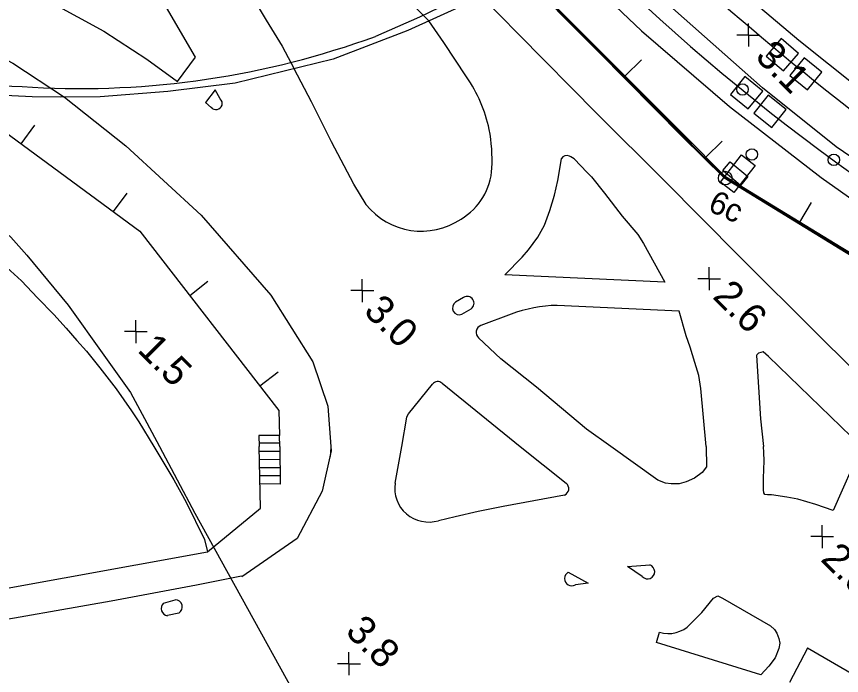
# Model space of a CAD drawing. Extents: x 1596643 to 1597288, y 13057194 to 13057957.
# Drawn here: x 1596778.7 to 1596850.7, y 13057439.2 to 13057496.7 of the extents above; entities that cross this region are included whole.
import ezdxf

# ---------------------------------------------------------------- set-up
doc = ezdxf.new("R2010")
doc.units = 0
for name, color, linetype in [('A spårmitt L', 7, 'Continuous'), ('B kabelbrunn mindre än 150 cm NK P', 7, 'Continuous'), ('BAS bro ej def L', 7, 'Continuous'), ('BAS fastighetsgräns samfällighet L', 7, 'Continuous'), ('BAS gränspunkt P', 7, 'Continuous'), ('BAS kajkant L', 7, 'Continuous'), ('BAS Level 15', 7, 'Continuous'), ('BAS Level 16', 7, 'Continuous'), ('BAS Level 18', 7, 'Continuous'), ('BAS Level 19', 7, 'Continuous'), ('BAS Level 37', 7, 'Continuous'), ('BAS markytetext T', 7, 'Continuous'), ('BAS stödmur fot L', 7, 'Continuous'), ('BAS stödmur krön L', 7, 'Continuous'), ('BAS trappa L', 7, 'Continuous'), ('BAS vägbanekant L', 7, 'Continuous'), ('BAS vägbanekant skymd L', 7, 'Continuous'), ('C skåp kartsymbol P', 7, 'Continuous'), ('D Plattform L', 7, 'Continuous'), ('E ktlstolpe omvriden centrum P', 7, 'Continuous'), ('E ktlstolpe T', 7, 'Continuous'), ('F balis P', 7, 'Continuous')]:
    doc.layers.add(name, color=color, linetype=linetype)

msp = doc.modelspace()

# ---------------------------------------------------------------- linework, layer by layer
at = {"layer": 'A spårmitt L'}
for centre, radius, start, end in [((1597037.43, 13057725.326), 301.08, 223.02589, 237.32659), ((1597036.217, 13057679.675), 257.932, 222.55623, 230.26648), ((1596962.077, 13057637.523), 190, 226.32199, 243.66622)]:
    msp.add_arc(centre, radius, start, end, dxfattribs=at)
at = {"layer": 'B kabelbrunn mindre än 150 cm NK P'}
msp.add_circle((1596842.862, 13057484.622), 0.5, dxfattribs=at)
msp.add_circle((1596842.862, 13057484.622), 0.5, dxfattribs=at)
at = {"layer": 'BAS bro ej def L'}
for points in [[(1596873.3, 13057525.881), (1596855.752, 13057517.013), (1596837.576, 13057507.614), (1596820.661, 13057499.012), (1596812.839, 13057495.445), (1596806.321, 13057492.938), (1596797.787, 13057490.834), (1596791.903, 13057490.118), (1596786.013, 13057489.635), (1596782.527, 13057489.62), (1596780.068, 13057489.652), (1596778.301, 13057489.746), (1596776.535, 13057489.911), (1596771.663, 13057490.412), (1596770.466, 13057490.58)], [(1596701.549, 13057432.918), (1596795.38, 13057449.947), (1596799.996, 13057453.759)]]:
    msp.add_lwpolyline(points, dxfattribs=at)
at = {"layer": 'BAS fastighetsgräns samfällighet L'}
for points in [[(1596648.373, 13057557.674), (1596669.206, 13057544.622), (1596696.734, 13057527.521), (1596729.513, 13057507.814), (1596732.164, 13057506.462), (1596736.214, 13057504.408), (1596755.642, 13057493.064), (1596764.143, 13057488.406), (1596767.219, 13057486.278), (1596770.569, 13057483.95), (1596773.669, 13057481.347), (1596776.843, 13057478.593), (1596778.218, 13057477.392), (1596779.593, 13057475.84), (1596783.217, 13057471.461), (1596786.315, 13057467.107), (1596788.639, 13057463.855), (1596790.088, 13057461.203), (1596791.175, 13057459.15)], [(1596791.175, 13057459.15), (1596794.26, 13057453.322), (1596807.425, 13057429.479), (1596823.36, 13057396.755), (1596830.03, 13057384.846), (1596831.279, 13057382.344)]]:
    msp.add_lwpolyline(points, dxfattribs=at)
at = {"layer": 'BAS gränspunkt P'}
for centre, radius in [((1596840.534, 13057482.562), 0.6), ((1596840.534, 13057482.562), 0.6), ((1596840.527, 13057482.557), 0.001), ((1596840.527, 13057482.557), 0.001)]:
    msp.add_circle(centre, radius, dxfattribs=at)
at = {"layer": 'BAS kajkant L'}
for points in [[(1596777.868, 13057474.754), (1596779.152, 13057473.579), (1596780.547, 13057472.119), (1596781.953, 13057470.649), (1596783.024, 13057469.466), (1596783.964, 13057468.394), (1596784.802, 13057467.445), (1596785.974, 13057465.986), (1596787.387, 13057464.171), (1596788.75, 13057462.254), (1596789.365, 13057461.296), (1596790.697, 13057459.15)], [(1596790.697, 13057459.15), (1596792.429, 13057456.23), (1596793.5, 13057454.271), (1596795.093, 13057451.023), (1596795.38, 13057449.947)]]:
    msp.add_lwpolyline(points, dxfattribs=at)
at = {"layer": 'BAS Level 15'}
for centre in [(1596842.04, 13057490.294), (1596842.04, 13057490.294), (1596850.006, 13057484.154), (1596850.006, 13057484.154)]:
    msp.add_circle(centre, 0.5, dxfattribs=at)
at = {"layer": 'BAS Level 16'}
for p, q in [((1596842.555, 13057495.041), (1596842.555, 13057496.041)), ((1596842.555, 13057495.041), (1596842.555, 13057496.041)), ((1596842.555, 13057495.041), (1596841.555, 13057495.041)), ((1596842.555, 13057495.041), (1596841.555, 13057495.041)), ((1596842.555, 13057495.041), (1596843.555, 13057495.041)), ((1596842.555, 13057495.041), (1596842.555, 13057494.041)), ((1596842.555, 13057495.041), (1596843.555, 13057495.041)), ((1596842.555, 13057495.041), (1596842.555, 13057494.041)), ((1596839.137, 13057473.777), (1596839.137, 13057474.777)), ((1596839.137, 13057473.777), (1596839.137, 13057474.777)), ((1596808.873, 13057472.738), (1596808.873, 13057473.738)), ((1596808.873, 13057472.738), (1596808.873, 13057473.738)), ((1596839.137, 13057473.777), (1596838.137, 13057473.777)), ((1596839.137, 13057473.777), (1596838.137, 13057473.777)), ((1596839.137, 13057473.777), (1596840.137, 13057473.777)), ((1596839.137, 13057473.777), (1596839.137, 13057472.777)), ((1596839.137, 13057473.777), (1596840.137, 13057473.777)), ((1596839.137, 13057473.777), (1596839.137, 13057472.777)), ((1596808.873, 13057472.738), (1596807.873, 13057472.738)), ((1596808.873, 13057472.738), (1596807.873, 13057472.738)), ((1596808.873, 13057472.738), (1596809.873, 13057472.738)), ((1596808.873, 13057472.738), (1596808.873, 13057471.738)), ((1596808.873, 13057472.738), (1596809.873, 13057472.738)), ((1596808.873, 13057472.738), (1596808.873, 13057471.738)), ((1596789.113, 13057469.166), (1596789.113, 13057470.166)), ((1596789.113, 13057469.166), (1596789.113, 13057470.166)), ((1596789.113, 13057469.166), (1596788.113, 13057469.166)), ((1596789.113, 13057469.166), (1596788.113, 13057469.166)), ((1596789.113, 13057469.166), (1596790.113, 13057469.166)), ((1596789.113, 13057469.166), (1596789.113, 13057468.166)), ((1596789.113, 13057469.166), (1596790.113, 13057469.166)), ((1596789.113, 13057469.166), (1596789.113, 13057468.166)), ((1596848.994, 13057451.271), (1596848.994, 13057452.271)), ((1596848.994, 13057451.271), (1596848.994, 13057452.271)), ((1596848.994, 13057451.271), (1596847.994, 13057451.271)), ((1596848.994, 13057451.271), (1596847.994, 13057451.271)), ((1596848.994, 13057451.271), (1596849.994, 13057451.271)), ((1596848.994, 13057451.271), (1596848.994, 13057450.271)), ((1596848.994, 13057451.271), (1596849.994, 13057451.271)), ((1596848.994, 13057451.271), (1596848.994, 13057450.271)), ((1596807.701, 13057440.183), (1596807.701, 13057441.183)), ((1596807.701, 13057440.183), (1596807.701, 13057441.183)), ((1596807.701, 13057440.183), (1596806.701, 13057440.183)), ((1596807.701, 13057440.183), (1596806.701, 13057440.183)), ((1596807.701, 13057440.183), (1596808.701, 13057440.183)), ((1596807.701, 13057440.183), (1596807.701, 13057439.183)), ((1596807.701, 13057440.183), (1596808.701, 13057440.183)), ((1596807.701, 13057440.183), (1596807.701, 13057439.183))]:
    msp.add_line(p, q, dxfattribs=at)
at = {"layer": 'BAS Level 18'}
for p, q in [((1596831.799, 13057491.466), (1596833.217, 13057492.877)), ((1596831.799, 13057491.466), (1596833.217, 13057492.877)), ((1596780.264, 13057487.163), (1596779.08, 13057485.551)), ((1596780.264, 13057487.163), (1596779.08, 13057485.551)), ((1596838.854, 13057484.378), (1596840.271, 13057485.789)), ((1596838.854, 13057484.378), (1596840.271, 13057485.789)), ((1596788.324, 13057481.244), (1596787.14, 13057479.632)), ((1596788.324, 13057481.244), (1596787.14, 13057479.632)), ((1596847.035, 13057478.72), (1596848.076, 13057480.428)), ((1596847.035, 13057478.72), (1596848.076, 13057480.428)), ((1596795.4, 13057473.521), (1596793.819, 13057472.297)), ((1596795.4, 13057473.521), (1596793.819, 13057472.297)), ((1596801.521, 13057465.613), (1596799.94, 13057464.389)), ((1596801.521, 13057465.613), (1596799.94, 13057464.389))]:
    msp.add_line(p, q, dxfattribs=at)
for points in [[(1596770.466, 13057490.58), (1596776.519, 13057487.432), (1596789.459, 13057477.929), (1596801.585, 13057462.263), (1596801.659, 13057460.099)], [(1596799.996, 13057453.759), (1596799.86, 13057459.15)]]:
    msp.add_lwpolyline(points, dxfattribs=at)
at = {"layer": 'BAS Level 19'}
msp.add_lwpolyline([(1596860.482, 13057478.28), (1596850.2, 13057485.288), (1596843.794, 13057490.442), (1596834.422, 13057498.747), (1596829.686, 13057503.602)], dxfattribs=at)
at = {"layer": 'BAS Level 37'}
for points in [[(1596840.526, 13057482.557), (1596822.999, 13057500.201)], [(1596872.455, 13057463.088), (1596840.526, 13057482.557)]]:
    msp.add_lwpolyline(points, dxfattribs=at)
at = {"layer": 'BAS stödmur fot L'}
msp.add_lwpolyline([(1596801.38, 13057521.802), (1596807.902, 13057515.293), (1596815.586, 13057507.536), (1596822.317, 13057500.788), (1596829.481, 13057493.571), (1596836.802, 13057486.17), (1596840.401, 13057482.599), (1596850.573, 13057476.382), (1596857.34, 13057472.24), (1596864.058, 13057468.19)], dxfattribs=at)
at = {"layer": 'BAS stödmur krön L'}
msp.add_lwpolyline([(1596864.123, 13057468.328), (1596857.409, 13057472.44), (1596850.653, 13057476.515), (1596840.554, 13057482.67), (1596836.91, 13057486.331), (1596829.604, 13057493.672), (1596822.422, 13057500.909), (1596815.38, 13057507.962), (1596808.004, 13057515.412), (1596801.503, 13057521.945)], dxfattribs=at)
at = {"layer": 'BAS trappa L'}
for points in [[(1596801.659, 13057460.099), (1596799.856, 13057460.107)], [(1596799.856, 13057460.107), (1596799.86, 13057459.15)], [(1596801.671, 13057459.15), (1596801.659, 13057460.099)], [(1596799.859, 13057459.456), (1596801.669, 13057459.464)], [(1596801.671, 13057459.15), (1596801.712, 13057455.858)], [(1596801.676, 13057458.686), (1596799.885, 13057458.696)], [(1596801.685, 13057457.979), (1596799.899, 13057457.991)], [(1596801.694, 13057457.272), (1596799.914, 13057457.285)], [(1596801.703, 13057456.565), (1596799.928, 13057456.579)], [(1596801.712, 13057455.858), (1596799.942, 13057455.874)]]:
    msp.add_lwpolyline(points, dxfattribs=at)
at = {"layer": 'BAS vägbanekant L'}
for p, q in [((1596847.714, 13057441.55), (1596846.154, 13057438.536)), ((1596855.549, 13057436.991), (1596847.714, 13057441.55))]:
    msp.add_line(p, q, dxfattribs=at)
for points in [[(1596884.542, 13057530.19), (1596879.403, 13057528.895), (1596877.377, 13057528.265), (1596871.837, 13057526.129), (1596868.719, 13057524.621), (1596858.752, 13057519.551), (1596850.365, 13057515.184), (1596847.614, 13057513.846), (1596841.051, 13057510.466), (1596834.743, 13057507.226), (1596828.139, 13057503.724), (1596822.677, 13057500.978), (1596818.182, 13057498.582), (1596816.389, 13057497.809), (1596813.852, 13057496.593), (1596810.012, 13057494.926)], [(1596855.481, 13057462.251), (1596854.127, 13057463.442), (1596848.649, 13057468.875), (1596841.763, 13057475.747), (1596835.201, 13057482.353), (1596829.337, 13057488.194), (1596822.512, 13057495.126), (1596819.302, 13057498.393)], [(1596817.971, 13057491.388), (1596815.984, 13057494.385), (1596814.683, 13057496.286)], [(1596809.195, 13057480.253), (1596808.127, 13057482.026), (1596806.195, 13057485.714), (1596804.444, 13057489.208), (1596802.917, 13057492.099)], [(1596796.475, 13057489.47), (1596796.041, 13057490.245), (1596795.193, 13057489.143)], [(1596782.883, 13057489.621), (1596788.233, 13057485.372), (1596794.817, 13057479.309), (1596800.892, 13057472.33), (1596804.557, 13057466.511), (1596805.878, 13057462.665), (1596806.128, 13057459.15)], [(1596795.193, 13057489.143), (1596795.675, 13057488.73)], [(1596821.319, 13057474.108), (1596822.82, 13057475.655), (1596823.372, 13057476.303), (1596824.191, 13057477.396), (1596824.765, 13057478.44), (1596825.239, 13057479.718), (1596825.632, 13057481.068), (1596825.933, 13057482.347), (1596826.143, 13057483.545), (1596826.248, 13057484.256)], [(1596827.345, 13057484.23), (1596827.06, 13057484.414), (1596826.938, 13057484.465)], [(1596827.345, 13057484.23), (1596828.488, 13057483.046), (1596828.862, 13057482.678), (1596830.003, 13057481.24), (1596831.558, 13057479.241), (1596832.901, 13057477.639), (1596833.395, 13057476.844), (1596835.258, 13057473.482)], [(1596835.258, 13057473.482), (1596821.319, 13057474.108)], [(1596817.705, 13057472.137), (1596817.015, 13057471.726), (1596817.015, 13057471.726)], [(1596817.568, 13057470.674), (1596818.369, 13057471.146), (1596818.369, 13057471.146)], [(1596836.518, 13057470.959), (1596825.877, 13057471.452), (1596825.877, 13057471.452)], [(1596821.85, 13057470.682), (1596819.216, 13057469.696), (1596819.216, 13057469.696)], [(1596838.859, 13057459.15), (1596838.403, 13057464.21), (1596838.225, 13057465.338), (1596837.896, 13057466.458), (1596837.466, 13057467.811), (1596837.135, 13057468.798), (1596836.518, 13057470.959)], [(1596820.947, 13057466.774), (1596819.02, 13057468.618)], [(1596830.561, 13057459.15), (1596828.446, 13057460.66), (1596824.064, 13057464.299), (1596820.947, 13057466.774)], [(1596852.428, 13057459.15), (1596844.301, 13057466.976), (1596843.835, 13057467.384), (1596843.632, 13057467.345), (1596843.428, 13057467.274), (1596843.285, 13057467.143), (1596843.254, 13057467.072), (1596843.613, 13057461.563), (1596843.882, 13057459.15)], [(1596812.756, 13057461.708), (1596812.753, 13057461.711), (1596812.896, 13057461.991), (1596814.999, 13057464.582)], [(1596815.831, 13057464.655), (1596822.659, 13057459.15)], [(1596812.307, 13057459.15), (1596812.756, 13057461.708)], [(1596806.128, 13057459.15), (1596806.157, 13057458.749), (1596805.37, 13057455.247), (1596803.203, 13057451.117), (1596798.361, 13057447.777)], [(1596806.11, 13057458.253), (1596806.143, 13057459.066)], [(1596811.744, 13057455.947), (1596812.307, 13057459.15)], [(1596822.659, 13057459.15), (1596826.661, 13057455.923)], [(1596838.859, 13057459.15), (1596838.901, 13057457.369), (1596838.523, 13057456.882), (1596837.851, 13057456.386), (1596837.118, 13057456.053), (1596836.508, 13057455.882), (1596835.827, 13057455.874), (1596835.319, 13057455.937), (1596834.669, 13057456.193), (1596830.561, 13057459.15)], [(1596852.428, 13057459.15), (1596849.945, 13057453.565), (1596848.453, 13057454.077), (1596846.879, 13057454.539), (1596845.924, 13057454.705), (1596844.573, 13057454.923), (1596844.228, 13057454.913), (1596844.004, 13057454.945), (1596843.913, 13057455.097), (1596843.884, 13057455.341), (1596843.887, 13057456.378), (1596843.922, 13057457.881), (1596843.904, 13057458.623), (1596843.882, 13057459.15)], [(1596826.516, 13057454.887), (1596821.175, 13057453.902), (1596818.977, 13057453.463), (1596816.977, 13057452.998), (1596815.521, 13057452.657)], [(1596833.301, 13057447.783), (1596832.013, 13057448.651), (1596833.955, 13057448.798)], [(1596826.839, 13057448.169), (1596828.574, 13057447.199), (1596827.465, 13057447.07)], [(1596648.373, 13057423.277), (1596663.816, 13057426.096), (1596679.993, 13057429.023), (1596685.87, 13057430.021), (1596688.259, 13057430.054), (1596691.205, 13057429.699), (1596694.781, 13057429.394), (1596696.752, 13057429.337), (1596706.646, 13057431.166), (1596724.237, 13057434.342), (1596748.193, 13057438.668), (1596774.702, 13057443.504), (1596786.954, 13057445.681), (1596794.408, 13057447.061), (1596798.344, 13057447.86)], [(1596837.485, 13057443.635), (1596838.484, 13057444.658), (1596839.524, 13057445.905), (1596839.881, 13057446.107), (1596840.297, 13057445.912), (1596844.496, 13057443.501), (1596844.841, 13057443.175), (1596845.043, 13057442.849), (1596845.214, 13057442.371), (1596845.294, 13057441.985), (1596845.211, 13057441.517), (1596844.883, 13057440.685), (1596844.353, 13057439.955), (1596843.639, 13057439.205), (1596834.543, 13057442.048), (1596834.8, 13057442.932)], [(1596791.537, 13057445.464), (1596792.554, 13057445.766)], [(1596792.865, 13057444.596), (1596791.889, 13057444.376)], [(1596847.714, 13057441.55), (1596846.154, 13057438.536)], [(1596855.549, 13057436.991), (1596847.714, 13057441.55)]]:
    msp.add_lwpolyline(points, dxfattribs=at)
for centre, radius, start, end in [((1596783.992, 13057581.524), 91.112, 249.32671, 267.55112), ((1596784.344, 13057565.037), 74.663, 266.74065, 290.10768), ((1596807.236, 13057484.04), 13.009, 12.23072, 34.39125), ((1596796.108, 13057489.075), 0.546, 217.93935, 47.59247), ((1596804.844, 13057484.041), 15.355, 357.72326, 10.33588), ((1596826.706, 13057483.988), 0.531, 64.06296, 149.66584), ((1596814.631, 13057483.757), 5.566, 300.93374, 356.642), ((1596814.032, 13057484.118), 6.192, 218.62657, 303.97238), ((1596817.341, 13057471.226), 0.597, 123.10435, 292.35403), ((1596818.023, 13057471.632), 0.597, 305.44836, 122.19874), ((1596826.262, 13057458.522), 12.936, 91.70552, 109.94224), ((1596819.436, 13057469.099), 0.636, 110.22931, 229.14462), ((1596815.45, 13057464.225), 0.575, 48.45756, 141.63577), ((1596814.635, 13057455.47), 2.93, 170.63091, 229.19299), ((1596826.268, 13057455.45), 0.615, 293.77336, 50.27793), ((1596814.693, 13057455.651), 3.106, 230.56523, 285.45895), ((1596833.757, 13057448.207), 0.623, 222.91743, 71.56505), ((1596827.151, 13057447.619), 0.632, 119.56506, 299.76736), ((1596791.945, 13057444.995), 0.623, 131.02118, 264.8389), ((1596792.543, 13057445.137), 0.629, 300.76086, 88.99811), ((1596835.58, 13057445.429), 2.616, 252.63161, 316.71882)]:
    msp.add_arc(centre, radius, start, end, dxfattribs=at)
at = {"layer": 'BAS vägbanekant skymd L'}
for points in [[(1596734.396, 13057519.666), (1596777.306, 13057499.983), (1596781.715, 13057497.89), (1596786.326, 13057495.383), (1596790.072, 13057492.925), (1596792.745, 13057490.975), (1596794.325, 13057493.107), (1596789.334, 13057501.668), (1596787.628, 13057504.442), (1596785.6, 13057507.247), (1596782.431, 13057511.175), (1596779.374, 13057514.259), (1596772.326, 13057520.755), (1596767.569, 13057524.751)], [(1596779.804, 13057520.386), (1596779.93, 13057519.81), (1596780.882, 13057519.084), (1596785.448, 13057515.85), (1596786.419, 13057514.971), (1596788.298, 13057512.787), (1596790.53, 13057510.185), (1596793.165, 13057507.021), (1596795.637, 13057503.676), (1596798.956, 13057498.914), (1596800.476, 13057496.326), (1596801.867, 13057494.083), (1596802.917, 13057492.099)], [(1596814.683, 13057496.286), (1596813.087, 13057497.887), (1596810.094, 13057500.859), (1596806.393, 13057504.292), (1596802.833, 13057507.48), (1596800.698, 13057509.218), (1596797.733, 13057511.591), (1596795.071, 13057513.698), (1596793.228, 13057514.936), (1596792.142, 13057515.595)], [(1596763.796, 13057499.681), (1596765.729, 13057498.803), (1596773.886, 13057494.982), (1596778.374, 13057492.579), (1596782.883, 13057489.615)]]:
    msp.add_lwpolyline(points, dxfattribs=at)
at = {"layer": 'C skåp kartsymbol P'}
for p, q in [((1596840.111, 13057482.205), (1596841.946, 13057484.578)), ((1596840.111, 13057482.205), (1596841.946, 13057484.578)), ((1596841.946, 13057484.578), (1596843.133, 13057483.661)), ((1596841.946, 13057484.578), (1596843.133, 13057483.661)), ((1596843.133, 13057483.661), (1596841.298, 13057481.288)), ((1596843.133, 13057483.661), (1596841.298, 13057481.288)), ((1596841.622, 13057482.933), (1596841.622, 13057482.933)), ((1596841.622, 13057482.933), (1596841.622, 13057482.933)), ((1596841.298, 13057481.288), (1596840.111, 13057482.205)), ((1596841.298, 13057481.288), (1596840.111, 13057482.205))]:
    msp.add_line(p, q, dxfattribs=at)
at = {"layer": 'D Plattform L'}
for points in [[(1596814.722, 13057513.813), (1596818.79, 13057509.576), (1596821.683, 13057506.586), (1596825.889, 13057502.375), (1596833.23, 13057495.42), (1596840.897, 13057488.807), (1596848.901, 13057482.619), (1596853.46, 13057479.369), (1596859.783, 13057475.256)], [(1596861.58, 13057487.322), (1596859.729, 13057484.577), (1596854.718, 13057488.355), (1596846.952, 13057494.556), (1596839.346, 13057501.034), (1596832, 13057507.739), (1596831.27, 13057508.417)]]:
    msp.add_lwpolyline(points, dxfattribs=at)
at = {"layer": 'E ktlstolpe omvriden centrum P'}
msp.add_lwpolyline([(1596840.326, 13057483.208), (1596840.968, 13057483.974), (1596842.501, 13057482.689), (1596841.858, 13057481.923)], close=True, dxfattribs=at)
msp.add_lwpolyline([(1596840.326, 13057483.208), (1596840.968, 13057483.974), (1596842.501, 13057482.689), (1596841.858, 13057481.923)], close=True, dxfattribs=at)
at = {"layer": 'F balis P'}
for p, q in [((1596845.407, 13057494.731), (1596844.11, 13057493.208)), ((1596845.407, 13057494.731), (1596844.11, 13057493.208)), ((1596846.93, 13057493.434), (1596845.407, 13057494.731)), ((1596846.93, 13057493.434), (1596845.407, 13057494.731)), ((1596845.52, 13057493.321), (1596845.52, 13057493.321)), ((1596845.52, 13057493.321), (1596845.52, 13057493.321)), ((1596845.633, 13057491.911), (1596846.93, 13057493.434)), ((1596845.633, 13057491.911), (1596846.93, 13057493.434)), ((1596844.11, 13057493.208), (1596845.633, 13057491.911)), ((1596844.11, 13057493.208), (1596845.633, 13057491.911)), ((1596847.409, 13057493.06), (1596846.161, 13057491.496)), ((1596847.409, 13057493.06), (1596846.161, 13057491.496)), ((1596848.973, 13057491.812), (1596847.409, 13057493.06)), ((1596848.973, 13057491.812), (1596847.409, 13057493.06)), ((1596842.248, 13057491.408), (1596840.988, 13057489.854)), ((1596842.248, 13057491.408), (1596840.988, 13057489.854)), ((1596843.802, 13057490.148), (1596842.248, 13057491.408)), ((1596843.802, 13057490.148), (1596842.248, 13057491.408)), ((1596846.161, 13057491.496), (1596847.725, 13057490.248)), ((1596846.161, 13057491.496), (1596847.725, 13057490.248)), ((1596847.567, 13057491.654), (1596847.567, 13057491.654)), ((1596847.567, 13057491.654), (1596847.567, 13057491.654)), ((1596847.725, 13057490.248), (1596848.973, 13057491.812)), ((1596847.725, 13057490.248), (1596848.973, 13057491.812)), ((1596840.988, 13057489.854), (1596842.542, 13057488.594)), ((1596840.988, 13057489.854), (1596842.542, 13057488.594)), ((1596842.395, 13057490.001), (1596842.395, 13057490.001)), ((1596842.395, 13057490.001), (1596842.395, 13057490.001)), ((1596842.542, 13057488.594), (1596843.802, 13057490.148)), ((1596842.542, 13057488.594), (1596843.802, 13057490.148)), ((1596844.268, 13057489.785), (1596843.03, 13057488.215)), ((1596844.268, 13057489.785), (1596843.03, 13057488.215)), ((1596845.838, 13057488.547), (1596844.268, 13057489.785)), ((1596845.838, 13057488.547), (1596844.268, 13057489.785)), ((1596844.434, 13057488.381), (1596844.434, 13057488.381)), ((1596844.434, 13057488.381), (1596844.434, 13057488.381)), ((1596844.6, 13057486.977), (1596845.838, 13057488.547)), ((1596844.6, 13057486.977), (1596845.838, 13057488.547)), ((1596843.03, 13057488.215), (1596844.6, 13057486.977)), ((1596843.03, 13057488.215), (1596844.6, 13057486.977))]:
    msp.add_line(p, q, dxfattribs=at)

# ---------------------------------------------------------------- texts
at = {"layer": 'BAS markytetext T'}
for s, p in [('3.1', (1596843.053, 13057493.054)), ('2.6', (1596839.347, 13057472.145)), ('3.0', (1596808.899, 13057470.852)), ('1.5', (1596789.168, 13057467.483)), ('2.0', (1596848.773, 13057449.229)), ('3.8', (1596807.303, 13057442.89))]:
    msp.add_text(s, height=2.5, rotation=315, dxfattribs=at).set_placement(p)
at = {"layer": 'E ktlstolpe T'}
msp.add_text('6c', height=1.999, rotation=335.54256, dxfattribs=at).set_placement((1596838.926, 13057479.755))

doc.saveas('drawing.dxf')
